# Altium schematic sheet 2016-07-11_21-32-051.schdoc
size 294 x 170 mm; SheetNumber: 1; SheetTotal: 1
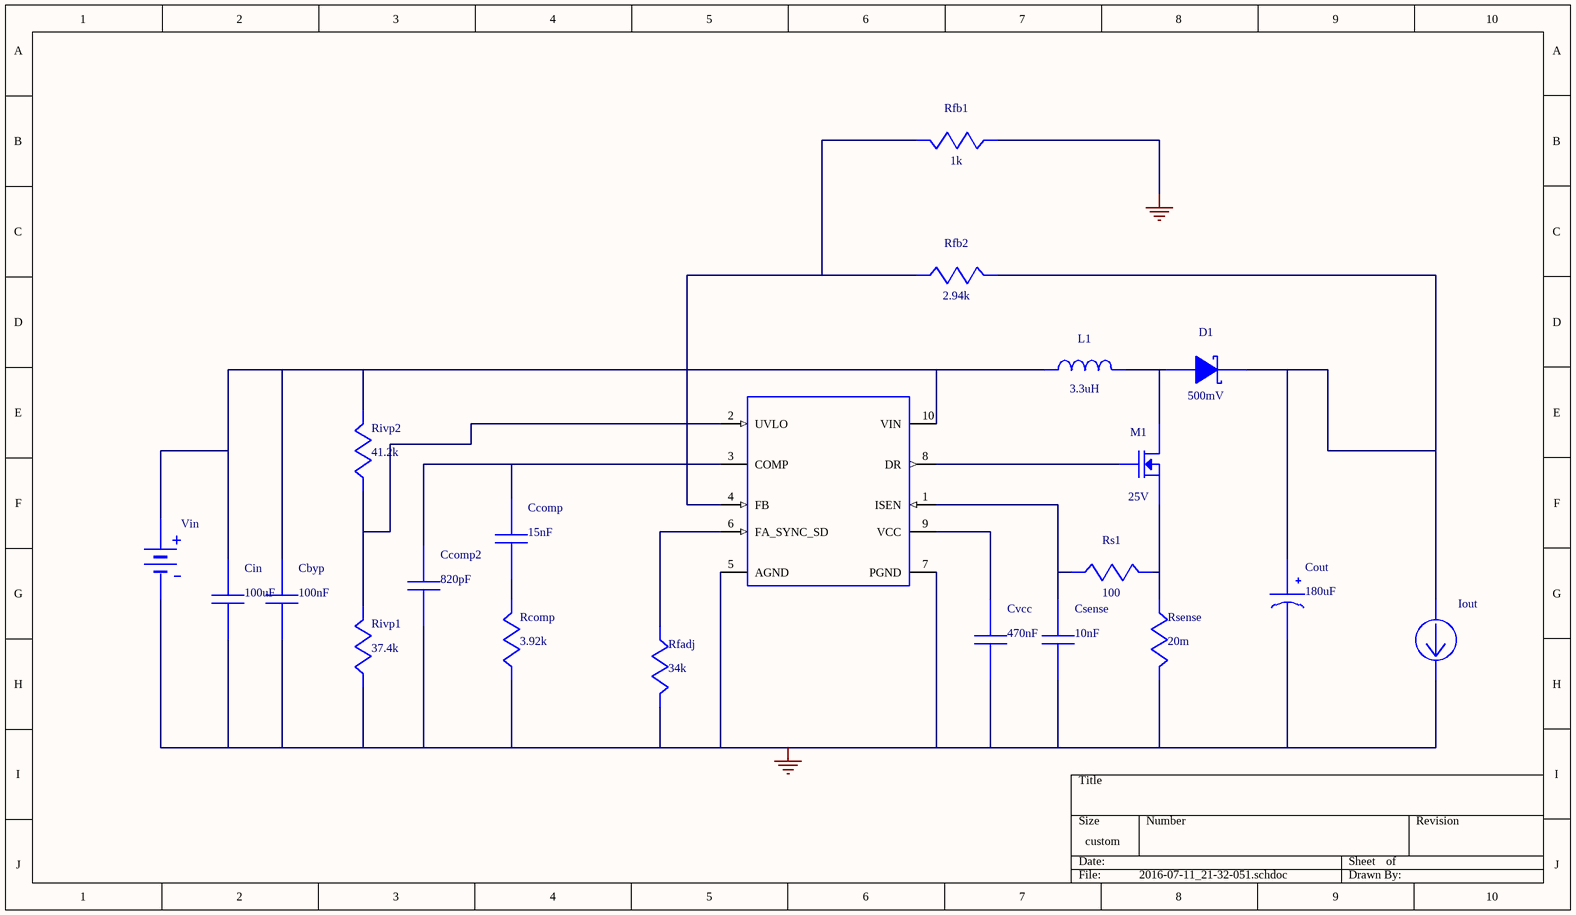
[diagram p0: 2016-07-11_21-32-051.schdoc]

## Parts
Cbyp  value 100nF  (hidden comment: GRM155R60J104KA01D)
Ccomp  value 15nF  (hidden comment: CC0805KRX7R9BB153)
Ccomp2  value 820pF  (hidden comment: CC0805KRX7R9BB821)
Cin  value 100uF  (hidden comment: GRM31CR60J107ME39L)
Cout  value 180uF  (hidden comment: 16SVPE180M)
Csense  value 10nF  (hidden comment: GRM216R71H103KA01D)
Cvcc  value 470nF  (hidden comment: GRM155C80J474KE19D)
D1  value 500mV  (hidden comment: B320-13-F)
Iout  WB_CURRENT_LOAD  (value not drawn)
L1  value 3.3uH  (hidden comment: SRN8040-3R3Y)
M1  value 25V  (hidden comment: CSD16323Q3)
Rcomp  value 3.92k  (hidden comment: CRCW04023K92FKED)
Rfadj  value 34k  (hidden comment: CRCW040234K0FKED)
Rfb1  value 1k  (hidden comment: CRCW04021K00FKED)
Rfb2  value 2.94k  (hidden comment: CRCW04022K94FKED)
Rivp1  value 37.4k  (hidden comment: CRCW040237K4FKED)
Rivp2  value 41.2k  (hidden comment: CRCW040241K2FKED)
Rs1  value 100  (hidden comment: CRCW0402100RFKED)
Rsense  value 20m  (hidden comment: CSR1206FK20L0)
U1  LM3481QMMX/NOPB  (value not drawn)
Vin  WB_BATTERY  (value not drawn)

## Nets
0: Cbyp.2 Ccomp2.2 Cin.2 Cout.2(-) Csense.2 Cvcc.2 Iout.2(-) Rcomp.2 Rfadj.1 Rfb1.2 Rivp1.2 Rsense.1 U1.5(AGND) U1.7(PGND) Vin.2(-)
NetCbyp_1: Cbyp.1 Cin.1 L1.1 Rivp2.1 U1.10(VIN) Vin.1(+)
NetCcomp_1: Ccomp.1 Ccomp2.1 U1.3(COMP)
NetCcomp_2: Ccomp.2 Rcomp.1
NetCout_1: Cout.1(+) D1.1(K) Iout.1(+) Rfb2.1
NetCsense_1: Csense.1 Rs1.2 U1.1(ISEN)
NetCvcc_1: Cvcc.1 U1.9(VCC)
NetD1_2: D1.2(A) L1.2 M1.5(Drain) M1.6(Drain) M1.7(Drain) M1.8(Drain) M1.9(Drain)
NetM1_1: M1.1(Source) M1.2(Source) M1.3(Source) Rs1.1 Rsense.2
NetM1_4: M1.4(Gate) U1.8(DR)
NetRfadj_2: Rfadj.2 U1.6(FA_SYNC_SD)
NetRfb1_1: Rfb1.1 Rfb2.2 U1.4(FB)
NetRivp1_1: Rivp1.1 Rivp2.2 U1.2(UVLO)

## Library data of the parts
Cbyp = GRM155R60J104KA01D: GRM155R60J104KA0; Manufacturer Name: MuRata
Ccomp = CC0805KRX7R9BB153: CC0805KRX7R9BB15; Manufacturer Name: Yageo America
Ccomp2 = CC0805KRX7R9BB821: CC0805KRX7R9BB82; Manufacturer Name: Yageo America
Cin = GRM31CR60J107ME39L: GRM31CR60J107ME3; Manufacturer Name: MuRata
Cout = 16SVPE180M: Manufacturer Name: Panasonic
Csense = GRM216R71H103KA01D: GRM216R71H103KA0; Manufacturer Name: MuRata
Cvcc = GRM155C80J474KE19D: GRM155C80J474KE1; Manufacturer Name: MuRata
D1 = B320-13-F: Manufacturer Name: Diodes Inc.
L1 = SRN8040-3R3Y: Manufacturer Name: Bourns
M1 = CSD16323Q3: Manufacturer Name: Texas Instruments
Rcomp = CRCW04023K92FKED: Manufacturer Name: Vishay-Dale
Rfadj = CRCW040234K0FKED: Manufacturer Name: Vishay-Dale
Rfb1 = CRCW04021K00FKED: Manufacturer Name: Vishay-Dale
Rfb2 = CRCW04022K94FKED: Manufacturer Name: Vishay-Dale
Rivp1 = CRCW040237K4FKED: Manufacturer Name: Vishay-Dale
Rivp2 = CRCW040241K2FKED: Manufacturer Name: Vishay-Dale
Rs1 = CRCW0402100RFKED: Manufacturer Name: Vishay-Dale
Rsense = CSR1206FK20L0: Manufacturer Name: Stackpole Electronics Inc
U1 = LM3481QMMX/NOPB: Manufacturer Name: Texas Instruments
